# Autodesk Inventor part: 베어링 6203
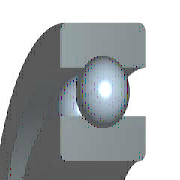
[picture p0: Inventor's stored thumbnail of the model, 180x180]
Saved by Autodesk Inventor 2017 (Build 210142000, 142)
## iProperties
IsCustomPart: 0
Created: 2016-05
Part Number: 베어링 6203
Material: 강, 연강
Description: 깊은 그루브 볼 베어링
Document SubType Name: Modeling
Standard: KS B 2023
Designer: mduedu
Standards Organization: KS
Language: ko-KR
Size Designation: 6203 - 17 x 40 x 12
Categories: <MemberInstance><Categories><Category DisplayName="샤프트 부품" InternalName="7f7aeb1f-a693-4053-b835-cee3144e0d98" Mnemonic="SHFT"><Category DisplayName="베어링" Inter
Density: 1 g/cm^3
Appearance: 노란색
Author: mduedu
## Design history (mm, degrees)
sketch "스케치" dims "d0" = 5.98 (= -0.26 x WD + 0.26 x BD)
  geometry: L1 (3.01, 14.25)-(8.99, 14.25); L2 (6, 14.25)-(6, 11.26); L3 (6, 14.25)-(6, 17.24); L4 (3.778, 12.249)-(0, 12.249); L5 (0, 8.5)-(12, 8.5); L6 (3.778, 16.251)-(0, 16.251); L7 (0, 20)-(12, 20); L8 (12, 8.5)-(12, 12.249); L9 (8.222, 12.249)-(12, 12.249); L10 (8.222, 16.251)-(12, 16.251); L11 (12, 20)-(12, 16.251); L12 (-1.4, 0)-(8.4, 0) reference; L13 (0, -0.3)-(0, 5.3) reference
  constraints: 22 end point, 4 point on line, 2 collinear, 2 perpendicular, 2 symmetric about line, 1 midpoint, 1 parallel, 14 other
  dimensions: "d9" = 17 diameter of L5 L12 (= WD); "d11" = 40 diameter of L7 L12 (= BD); "d12" = 12 distance between parallel lines of L8 L13 (= KB); "d13" = 24.498 diameter of L9 L12 (= 0.326 x BD + 0.674 x WD)
revolve "본체" stored, may be unused: angle "d6" = 90 deg
revolve "볼" stored, may be unused: angle "d7" = 90 deg
pattern_circular "IDS_ARRAYBALL[SIMPL:T]" dims angle "d3" = 360 deg
body "Solid1"
fillet "모깎기1" dims "d1" = 0.6 (= KRS)
other parameters: "WD" = 17 [user parameter; used in 5 equation terms], "BD" = 40 [user parameter; used in 5 equation terms], "KB" = 12 [user parameter; used in 1 equation term], "KRS" = 0.6 [user parameter; used in 1 equation term], "d4" = 0, "d5" = 0, "d8" = 0, "d14" = 0, "d15" = 0, "BBA" = 0 [user parameter], "BC0" = 4750000 [user parameter], "BC" = 9560000 [user parameter], "WR" = 8.5 (= 0.5 x WD) [user parameter]
